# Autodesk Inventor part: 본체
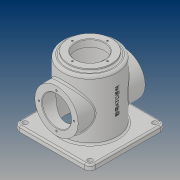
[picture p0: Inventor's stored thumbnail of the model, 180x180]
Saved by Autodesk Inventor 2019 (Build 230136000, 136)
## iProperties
Created: 2019-03
Part Number: 본체
Material: 일반
Document SubType Name: Modeling
Designer: PC312-14
Density: 1 g/cm^3
Appearance: 기본값
Author: PC312-14
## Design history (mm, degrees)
sketch "스케치1"
  geometry: C1 r 50 at (0, 0); 1 further point
  constraints: 1 centre point, 1 coincident
  dimensions: "d0" = 100 diameter of C1
extrude "돌출1" new body sketch "스케치1" distance "d1" = 110; taper "d2" = 0 deg
sketch "스케치2"
  geometry: C1 r 45 at (0, 0); 1 further point
  constraints: 1 centre point, 1 coincident
  dimensions: "d3" = 90 diameter of C1
extrude "돌출2" cut sketch "스케치2" distance "d4" = 102; taper "d5" = 0 deg
sketch "스케치3"
  geometry: L1 (-70, 70)-(70, 70); L2 (70, 70)-(70, -70); L3 (70, -70)-(-70, -70); L4 (-70, -70)-(-70, 70); L5 (-70, 70)-(70, -70); L6 (70, 70)-(-70, -70); C1 r 45 at (0, 0) reference; 1 further point
  constraints: 12 end point, 2 midpoint, 2 parallel, 1 horizontal, 1 perpendicular
  dimensions: "d6" = 140 distance of L2.end L3.end; "d7" = 140 distance of L1.end L2.end
extrude "돌출3" join sketch "스케치3" distance "d8" = 10; taper "d9" = 0 deg
node "작업 평면1"
sketch "스케치4"
  geometry: L1 (70, -10)-(-70, -10) reference; L2 (-70, 0)-(70, 0) reference; C1 r 40 at (0, 50); 2 further points
  constraints: 1 centre point, 1 midpoint, 1 vertical alignment
  dimensions: "d11" = 80 diameter of C1; "d12" = 60 distance from line of L1 C1.centre
extrude "돌출4" join sketch "스케치4" stored distance "d13" = 12; taper "d14" = 0 deg
sketch "스케치5" dims "d15" = 65
  geometry: C1 r 40 at (0, 0) reference; 3 further points
  constraints: 2 vertical alignment, 1 coincident, 2 other
hole "구멍1" sketch "스케치5" at (0, 32.5) diameter "d16" = 3.242; stored, may be unused: countersink angle "d20" = 90 deg, drill point angle "d22" = 118 deg; dims "d17" = 8, "d18" = 4, "d19" = 2, "d21" = 10
sketch "스케치6"
  geometry: C1 r 40 at (0, 0) reference; C2 r 27 at (0, 0); 1 further point
  constraints: 1 centre point, 1 coincident
  dimensions: "d26" = 54 diameter of C2
extrude "돌출5" cut sketch "스케치6" stored distance "d27" = 12; taper "d28" = 0 deg
sketch "스케치7"
  geometry: C1 r 40 at (0, 0); 1 further point
  constraints: 1 centre point, 1 coincident
  dimensions: "d29" = 80 diameter of C1
extrude "돌출6" join sketch "스케치7" distance "d30" = 5; taper "d31" = 0 deg
sketch "스케치8" dims "d32" = 65
  geometry: 3 further points
  constraints: 2 vertical alignment, 1 coincident, 2 other
hole "구멍2" sketch "스케치8" at (0, 32.5) diameter "d33" = 3.242; stored, may be unused: countersink angle "d37" = 90 deg, drill point angle "d39" = 118 deg; dims "d34" = 8, "d35" = 4, "d36" = 2, "d38" = 10
sketch "스케치9"
  geometry: C1 r 27 at (0, 0); 1 further point
  constraints: 1 centre point, 1 coincident
  dimensions: "d43" = 54 diameter of C1
extrude "돌출7" cut sketch "스케치9" distance "d44" = 13; taper "d45" = 0 deg
fillet "모깎기1" dims "d46" = 10
sketch "스케치10"
  geometry: A1 r 10 centre (60, -60) between (60, -70) and (70, -60) reference; A2 r 10 centre (60, 60) between (70, 60) and (60, 70) reference; A3 r 10 centre (-60, 60) between (-60, 70) and (-70, 60) reference; A4 r 10 centre (-60, -60) between (-70, -60) and (-60, -70) reference; 5 further points
  constraints: 4 coincident
hole "구멍3" sketch "스케치10" at (60, -60), (60, 60), (-60, 60), (-60, -60) diameter "d47" = 9; stored, may be unused: countersink angle "d51" = 90 deg, drill point angle "d53" = 118 deg; dims "d48" = 20, "d49" = 4, "d50" = 2, "d52" = 27.3
chamfer "모따기1" distance "d55" = 1; stored, may be unused: second distance "d56" = 2, angle "d57" = 45 deg
fillet "모깎기5" dims "d60" = 3
fillet "모깎기6" dims "d61" = 3
node "작업 평면2"
sketch "스케치11"
  geometry: L1 (-10, -60)-(-10, 60) reference; L2 (0, -60)-(0, 60) reference; 3 further points
  constraints: 1 horizontal alignment, 1 midpoint, 1 other
  dimensions: "d63" = 70 distance from line of L1 point (60, 0)
feature "엠보싱1" sketch "스케치11" dims "d64" = 0.5, "d65" = 0
fillet "모깎기7" dims "d66" = 5
fillet "모깎기8" dims "d67" = 3
fillet "모깎기9" dims "d68" = 3
node "솔리드1"
pattern_circular "원형 패턴1" dims angle "d24" = 360 deg
mirror "미러1"
pattern_circular "원형 패턴2" dims angle "d41" = 360 deg
other parameters: "d10" = 62, "d62" = 54
